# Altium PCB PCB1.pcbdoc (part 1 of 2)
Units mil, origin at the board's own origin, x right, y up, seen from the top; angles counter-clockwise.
Board outline 5175 x 2060 mil, 4 copper layers (Top Layer, Inner1, Inner2, Bottom Layer), stack 62.447 mil thick; 102 components, 59 nets, 316 pads, 177 vias.
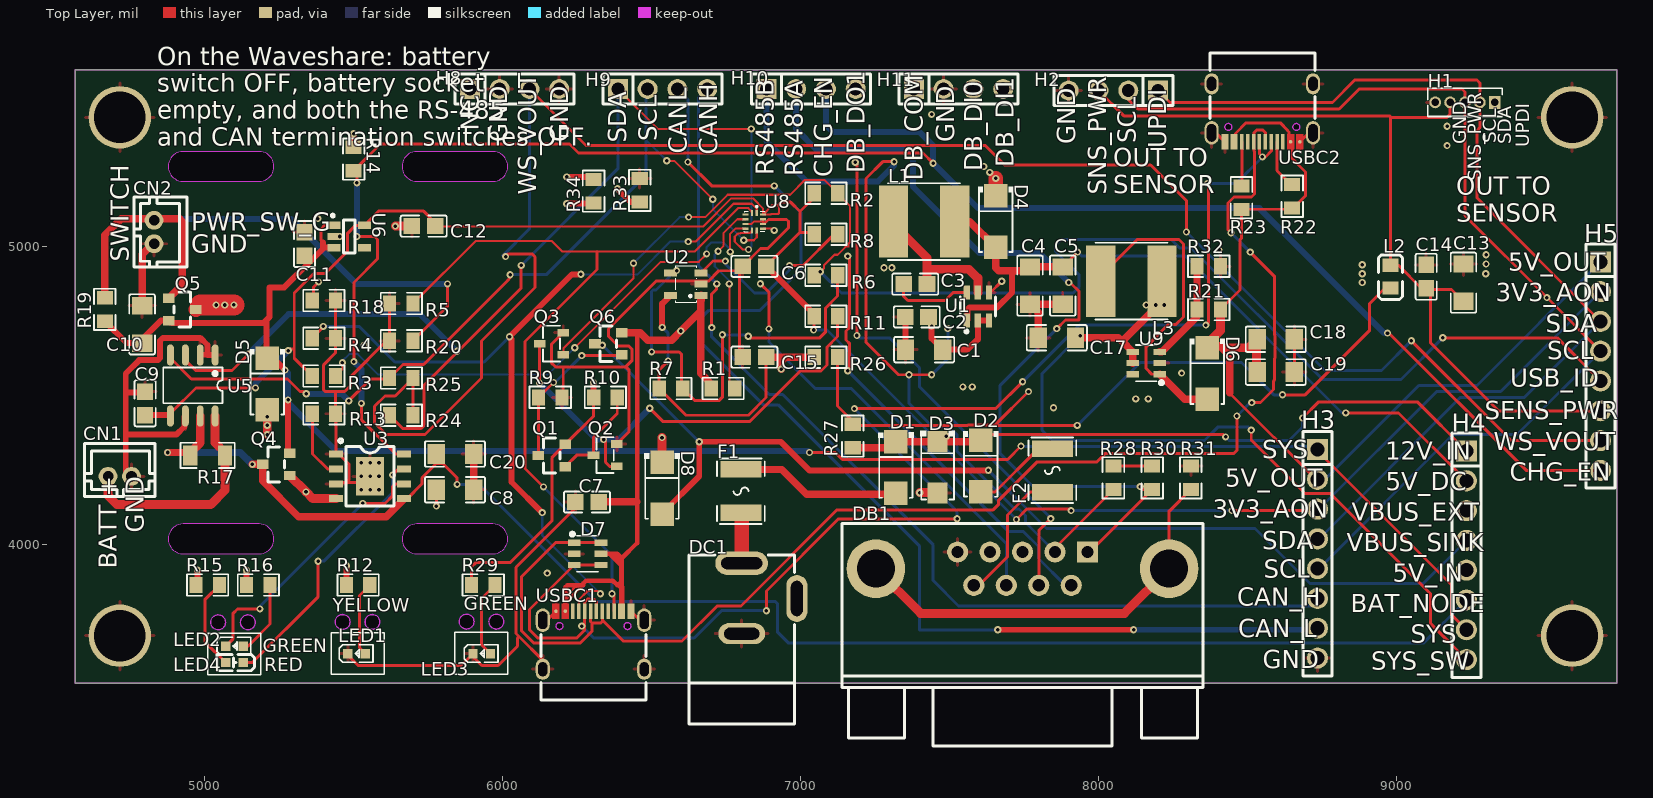
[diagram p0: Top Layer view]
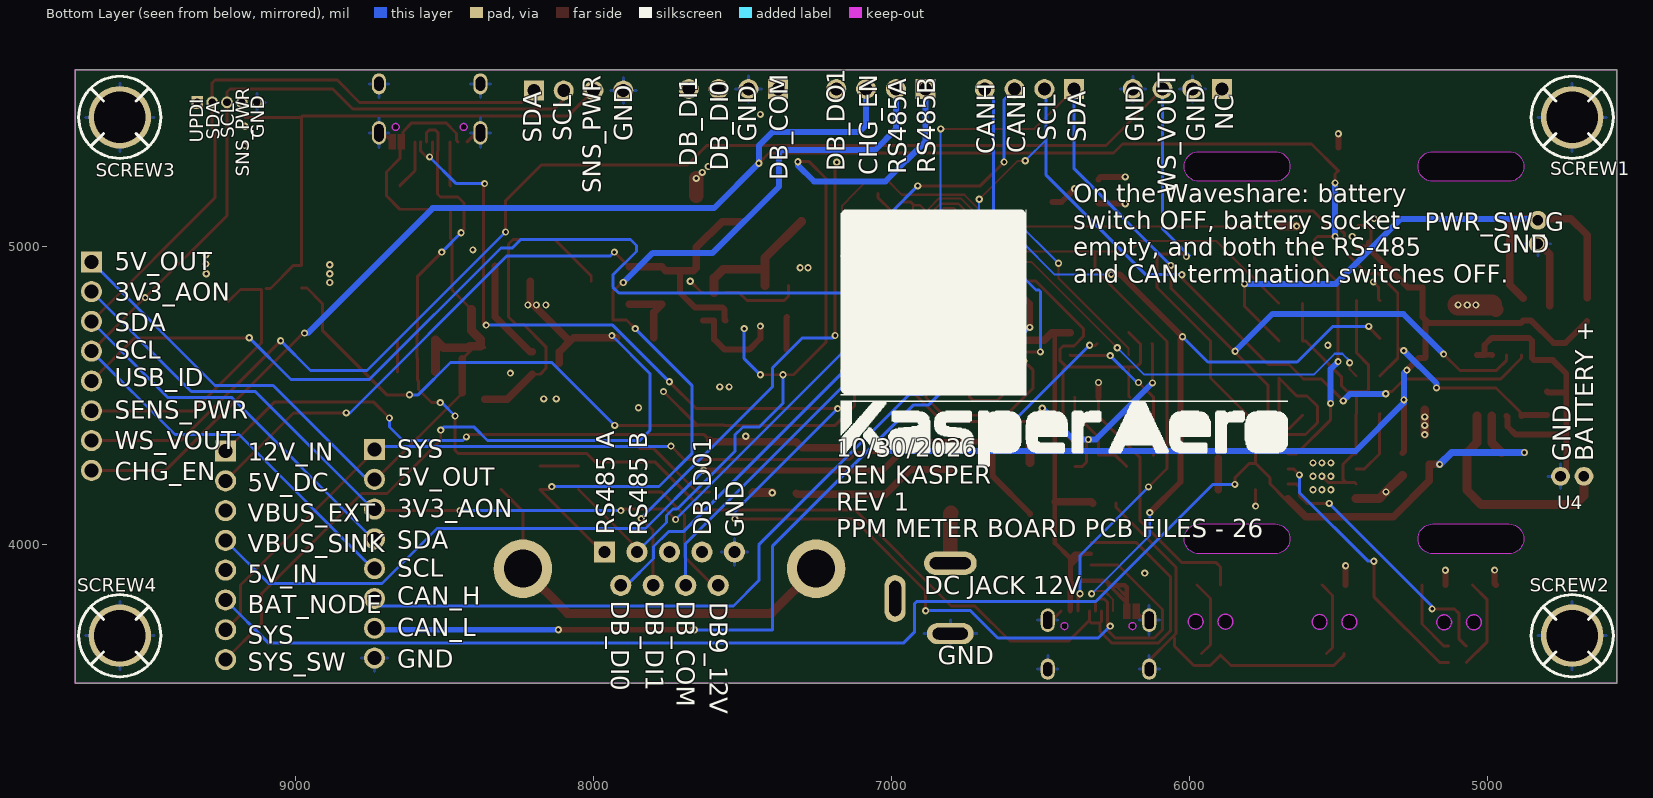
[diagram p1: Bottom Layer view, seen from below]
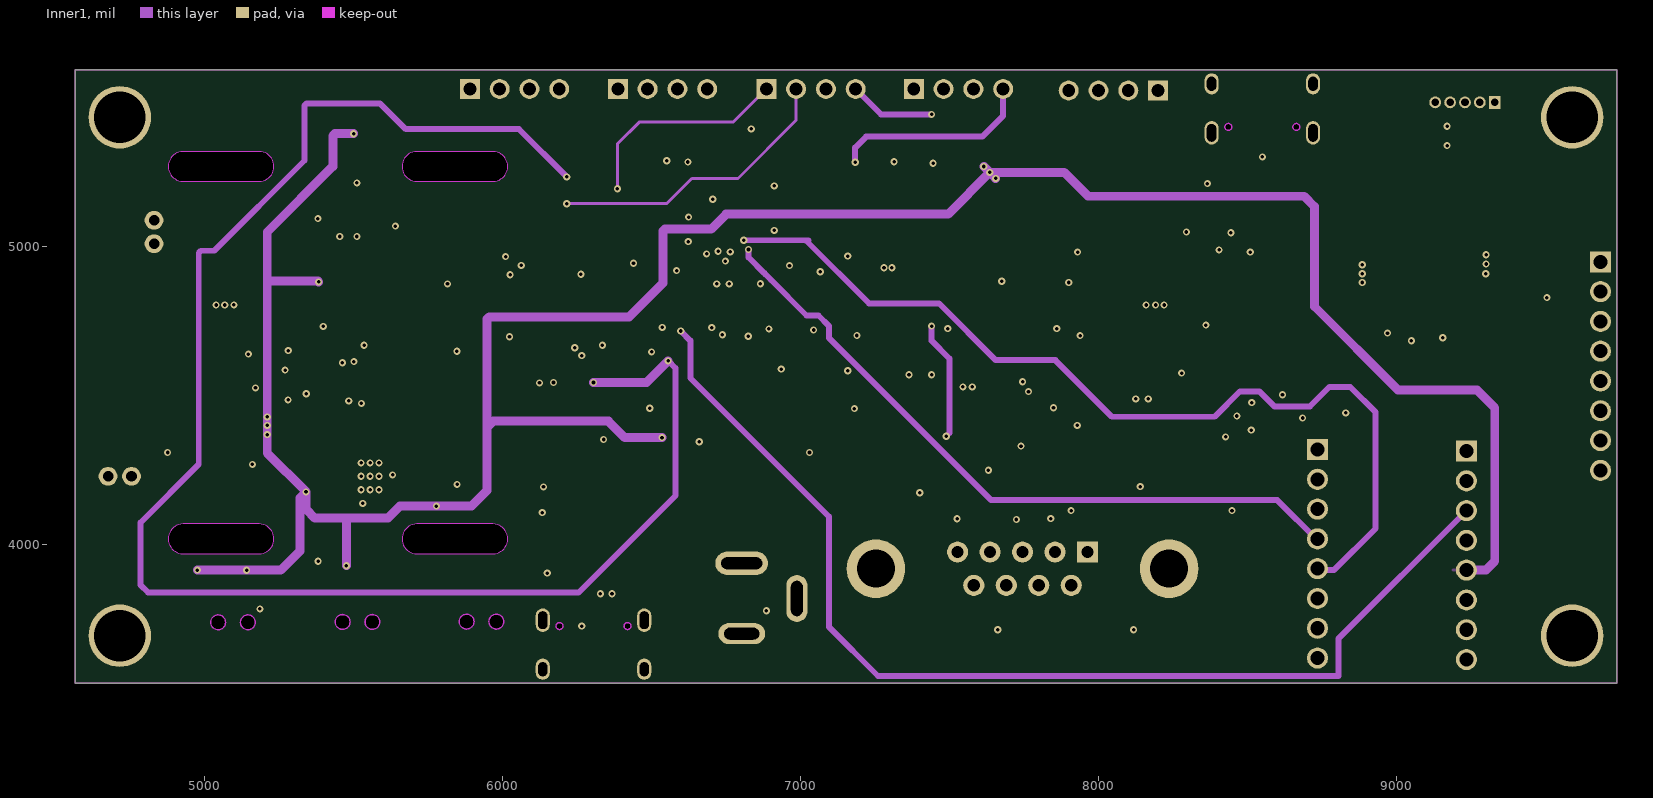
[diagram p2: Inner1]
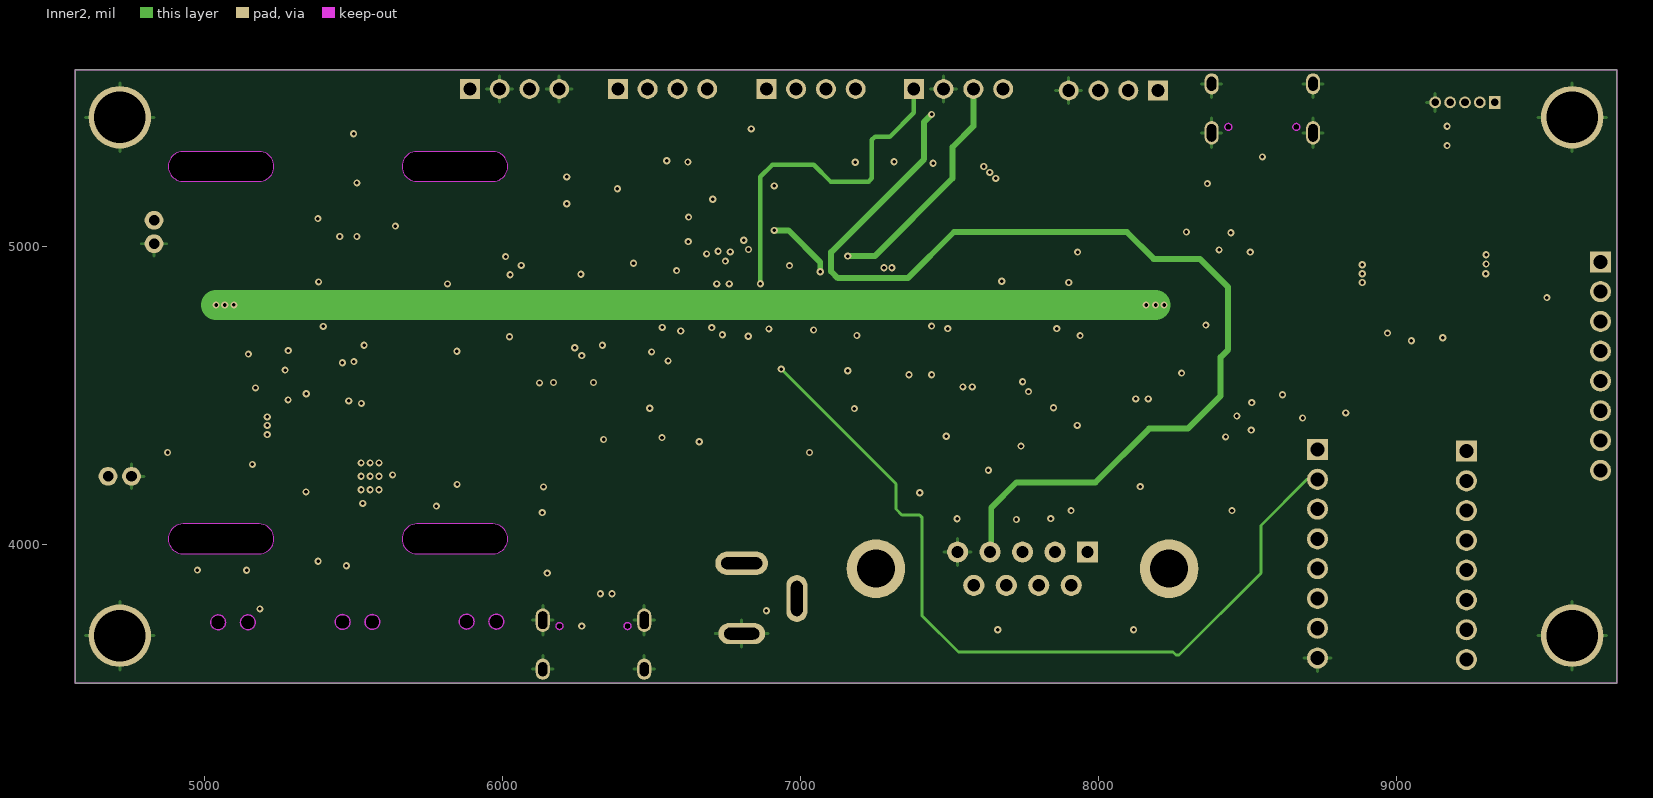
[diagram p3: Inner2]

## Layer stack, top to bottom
Top Layer: signal copper 1.378
Dielectric1: surface 8.283, 7628 RC49% 8.6mil, Dk 0
Inner1: signal copper 0.598
Dielectric2: surface 41.929, 1.1mm H/HOZ Copper, Dk 0
Inner2: signal copper 0.598
Dielectric3: surface 8.283, 7628 RC49% 8.6mil, Dk 0
Bottom Layer: signal copper 1.378

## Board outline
4565,5595 4565,3535 9740,3535 9740,5595
cut-out: 4927.5,5320 ccw(c4927.5,5270) 4877.5,5270 ccw(c4927.5,5270) 4927.5,5220 5182.5,5220 ccw(c5182.5,5270) 5232.5,5270 ccw(c5182.5,5270) 5182.5,5320
cut-out: 5712.5,5320 ccw(c5712.5,5270) 5662.5,5270 ccw(c5712.5,5270) 5712.5,5220 5967.5,5220 ccw(c5967.5,5270) 6017.5,5270 ccw(c5967.5,5270) 5967.5,5320
cut-out: 4927.5,4070 ccw(c4927.5,4020) 4877.5,4020 ccw(c4927.5,4020) 4927.5,3970 5182.5,3970 ccw(c5182.5,4020) 5232.5,4020 ccw(c5182.5,4020) 5182.5,4070
cut-out: 5712.5,4070 ccw(c5712.5,4020) 5662.5,4020 ccw(c5712.5,4020) 5712.5,3970 5967.5,3970 ccw(c5967.5,4020) 6017.5,4020 ccw(c5967.5,4020) 5967.5,4070
cut-out: 5070,3740 cw(c5045,3740) 5020,3740 cw(c5045,3740)
cut-out: 5170,3740 cw(c5145,3740) 5120,3740 cw(c5145,3740)
cut-out: 5488,3741.25 cw(c5463,3741.25) 5438,3741.25 cw(c5463,3741.25)
cut-out: 5588,3741.25 cw(c5563,3741.25) 5538,3741.25 cw(c5563,3741.25)
cut-out: 5904,3742.25 cw(c5879,3742.25) 5854,3742.25 cw(c5879,3742.25)
cut-out: 6004,3742.3 cw(c5979,3742.3) 5954,3742.3 cw(c5979,3742.3)

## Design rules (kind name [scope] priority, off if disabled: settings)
BoardOutlineClearance copperThickness1oz [All] p0: genericclearance=10 ignorepadtopadclearanceinfootprint=FALSE except(0: Arc-SplitContinuation Track-SplitContinuation SMDPad-SplitContinuation THPad-SplitContinuation Via-SplitContinuation Fill-SplitContinuation Poly-SplitContinuation Region-SplitContinuation Text-SplitContinuation)
BoardOutlineClearance copperThickness2oz [All] p0: genericclearance=10 ignorepadtopadclearanceinfootprint=FALSE except(0: Arc-SplitContinuation Track-SplitContinuation SMDPad-SplitContinuation THPad-SplitContinuation Via-SplitContinuation Fill-SplitContinuation Poly-SplitContinuation Region-SplitContinuation Text-SplitContinuation)
BoardOutlineClearance safeClearance1 [All] p0: genericclearance=10 ignorepadtopadclearanceinfootprint=FALSE except(0: Arc-SplitContinuation Track-SplitContinuation SMDPad-SplitContinuation THPad-SplitContinuation Via-SplitContinuation Fill-SplitContinuation Poly-SplitContinuation Region-SplitContinuation Text-SplitContinuation)
BoardOutlineClearance otherClearance [All] p0: genericclearance=10 ignorepadtopadclearanceinfootprint=FALSE except(0: Arc-SplitContinuation Track-SplitContinuation SMDPad-SplitContinuation THPad-SplitContinuation Via-SplitContinuation Fill-SplitContinuation Poly-SplitContinuation Region-SplitContinuation Text-SplitContinuation)
Clearance copperThickness1oz [All] p1: gap=7 ignorepadtopadclearanceinfootprint=FALSE
Clearance copperThickness2oz [All] p1: gap=7 ignorepadtopadclearanceinfootprint=FALSE
Clearance safeClearance1 [All] p1: gap=7 ignorepadtopadclearanceinfootprint=FALSE
Clearance otherClearance [All] p1: gap=7 ignorepadtopadclearanceinfootprint=FALSE
DiffPairsRouting differentialPair [All] p1: maxuncoupledlength=10 minlimit=6 maxlimit=Infinity mostfreqgap=6 toplayer_minwidth=5 toplayer_prefwidth=10 toplayer_maxwidth=100 bottomlayer_minwidth=5 bottomlayer_prefwidth=10 bottomlayer_maxwidth=100 midlayer1_minwidth=5 midlayer1_prefwidth=10 midlayer1_maxwidth=100 midlayer2_minwidth=5 midlayer2_prefwidth=10 midlayer2_maxwidth=100
PasteMaskExpansion pasteMaskExpansion [All] p1: expansion=0
PlaneConnect innerPlane [All] p1: planeconnectstyle=Relief reliefexpansion=20 reliefentries=4 reliefconductorwidth=10 reliefairgap=10
PolygonConnect copperRegion [All] p1: connectstyle=Relief reliefentries=4 reliefconductorwidth=10 polygonreliefangle="90 Angle" airgapwidth=10
RoutingVias viaSize [All] p1: viastyle="Through Hole" holewidth=12.0078 minholewidth=11.811 maxholewidth=248.0314 width=12.0078 minwidth=11.811 maxwidth=248.0314
SolderMaskExpansion solderMaskExpansion [IsVia] p1: useseparateexpansions=TRUE expansion=-1000 expansionbottom=-1000
SolderMaskExpansion solderMaskExpansion [All] p2: useseparateexpansions=TRUE expansion=2 expansionbottom=2
Width copperThickness1oz [All] p1: maxlimit=100 minlimit=5 preferedwidth=10
Width copperThickness2oz [All] p1: maxlimit=100 minlimit=8 preferedwidth=10

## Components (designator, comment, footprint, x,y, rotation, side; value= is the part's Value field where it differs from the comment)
C1 "22uF" C1206 7415,4655 r0 top
C2 "100nF" C0805 7390,4765 r0 top
C3 "100nF" C0805 7385,4875 r180 top
C4 "22uF" C1206 7770,4870 r90 top
C5 "22uF" C1206 7880,4870 r90 top
C6 "100nF" C0805 6845,4935 r0 top
C7 "1uF" C0805 6283.2,4143.7 r180 top
C8 "22uF" C1206 5840,4185 r180 top
C9 "100nF" C0805 4800,4475 r270 top
C10 "22uF" C1206 4790,4740 r270 top
C11 "1uF" C0805 5335,5010 r270 top
C12 "1uF" C0805 5735,5070 r0 top
C13 "22uF" C1206 9225,4880 r90 top
C14 "100nF" C0805 9100,4900 r270 top
C15 "100nF" C0805 6845,4630 r0 top
C17 "22uF" C1206 7860,4695 r180 top
C18 "22uF" C1206 8595,4690 r0 top
C19 "22uF" C1206 8595,4580 r0 top
C20 "22uF" C1206 5840,4305 r180 top
CN1 "B2B-PH-K-S(LF)(SN)" CONN-TH_B2B-PH-K-S 4715,4230 r0 top
CN2 "B2B-PH-K-S(LF)(SN)" CONN-TH_B2B-PH-K-S 4830,5050 r270 top
D1 "SS34" SMA_L4.3-W2.6-LS5.2-RD 7320,4260 r270 top
D2 "SS34" SMA_L4.3-W2.6-LS5.2-RD 7605,4264.23 r270 top
D3 "SMAJ18A" SMA_L4.4-W2.6-LS5.0-RD 7460,4260 r270 top
D4 "SS34" SMA_L4.3-W2.6-LS5.2-RD 7655,5085 r270 top
D5 "SS34" SMA_L4.3-W2.6-LS5.2-RD 5210,4540 r270 top
D6 "SS34" SMA_L4.3-W2.6-LS5.2-RD 8365,4575 r270 top
D7 "USBLC6-2SC6" SOT-23-6_L2.9-W1.6-P0.95-LS2.8-BL 6285,3970 r270 top
D8 "SS34" SMA_L4.3-W2.6-LS5.2-RD 6535,4190 r270 top
DB1 "A-DF 09 A/KG-T2S" DB9-TH_DB9F_C9900018961 7745,3920 r0 top
DC1 "PJ-002AH" DC-IN-TH_PJ-002AH 6895,3820 r270 top
F1 "BSMD1812-150-33V" F1812 6800,4180 r90 top
F2 "BSMD1812-150-33V" F1812 7845,4250 r90 top
H1 "GRPB051VWVN-RC" HDR-TH_5P-P1.27-V-M-1 9230,5485 r180 top
H2 "" HDR-TH_4P-P2.54-V-M 8050,5525 r180 top
H3 "" HDR-TH_8P-P2.54-V-F-1 8735,3970 r270 top
H4 "" HDR-TH_8P-P2.54-V-F-1 9235,3965 r270 top
H5 "" HDR-TH_8P-P2.54-V-F-1 9685,4600 r270 top
H8 "" HDR-TH_4P-P2.54-V-M 6040,5530 r0 top
H9 "" HDR-TH_4P-P2.54-V-M 6536.67,5530 r0 top
H10 "" HDR-TH_4P-P2.54-V-M 7035,5530 r0 top
H11 "" HDR-TH_4P-P2.54-V-M 7530,5530 r0 top
L1 "6.8uH" IND-SMD_L6.0-W6.0_SMNR6045 7415,5085 r180 top
L2 "BLM21PG221SN1D" L0805 8980,4900 r90 top
L3 "6.8uH" IND-SMD_L6.0-W6.0_SMNR6045 8110,4885 r0 top
LED1 "NCD0603Y2" LED0603-RD 5510,3635 r0 top
LED2 "KT-0603G" LED0603-RD 5100,3660 r0 top
LED3 "KT-0603G" LED0603-RD 5930,3635 r0 top
LED4 "KT-0603R" LED-SMD_L1.6-W0.8-R-RD 5100,3605 r180 top
Q1 "AO3401A" SOT-23_L2.9-W1.3-P1.90-LS2.4-BR 6165,4300 r0 top
Q2 "2N7002" SOT-23-3_L2.9-W1.3-P1.90-LS2.4-BR 6344.1,4300.97 r0 top
Q3 "2N7002" SOT-23-3_L2.9-W1.3-P1.90-LS2.4-BR 6164.1,4675 r0 top
Q4 "AO3401A" SOT-23_L2.9-W1.3-P1.90-LS2.4-BR 5240,4270 r0 top
Q5 "AO3401A" SOT-23_L2.9-W1.3-P1.90-LS2.4-BR 4925,4790 r180 top
Q6 "AO3401A" SOT-23_L2.9-W1.3-P1.90-LS2.4-BR 6355,4675 r0 top
R1 "910kΩ" R0805 6740,4525 r0 top
R2 "100kΩ" R0805 7085,5180 r0 top
R3 "100kΩ" R0805 5400,4566.67 r0 top
R4 "5.1kΩ" R0805 5400,4693.33 r0 top
R5 "5.1kΩ" R0805 5660,4810 r180 top
R6 "0Ω" R0805 7085,4905 r0 top
R7 "100kΩ" R0805 6565,4525 r0 top
R8 "10kΩ" R0805 7085,5042.5 r0 top
R9 "100kΩ" R0805 6160,4495 r0 top
R10 "100kΩ" R0805 6345,4495 r0 top
R11 "100kΩ" R0805 7085,4767.5 r0 top
R12 "1kΩ" R0805 5515,3865 r0 top
R13 "2kΩ" R0805 5400,4440 r0 top
R14 "10kΩ" R0805 5500,5295 r270 top
R15 "1kΩ" R0805 5010,3865 r0 top
R16 "1kΩ" R0805 5180,3865 r0 top
R17 "50mΩ" R1206 5010,4300 r180 top
R18 "100kΩ" R0805 5400,4820 r180 top
R19 "1kΩ" R0805 4665,4790 r90 top
R20 "0Ω" R0805 5660,4685 r180 top
R21 "75kΩ" R0805 8370,4790 r180 top
R22 "10kΩ" R0805 8650,5170 r90 top
R23 "10kΩ" R0805 8480,5165 r90 top
R24 "10kΩ" R0805 5660,4435 r0 top
R25 "10kΩ" R0805 5660,4560 r0 top
R26 "0Ω" R0805 7085,4630 r0 top
R27 "0Ω" R0805 7175,4365 r90 top
R28 "0Ω" R0805 8050,4225 r270 top
R29 "1kΩ" R0805 5935,3865 r0 top
R30 "120Ω" R0805 8180,4225 r90 top
R31 "0Ω" R0805 8310,4225 r90 top
R32 "10kΩ" R0805 8370,4935 r0 top
R33 "560Ω" R0805 6460,5190 r90 top
R34 "560Ω" R0805 6305.39,5187.1 r90 top
SCREW1 "" Screw-Hole-M4 4715,5434.98 r180 bottom
SCREW2 "" Screw-Hole-M4 4715,3695 r180 bottom
SCREW3 "" Screw-Hole-M4 9590,5435 r180 bottom
SCREW4 "" Screw-Hole-M4 9590,3695 r180 bottom
U1 "AP63205WU-7" TSOT-23-6_L2.9-W1.6-P0.95-LS2.8-BL 7595,4800 r0 top
U2 "TPS2041BDBVR" SOT-23-5_L3.0-W1.7-P0.95-LS2.8-BR 6615,4875 r0 top
U3 "TP4056-42-ESOP8" ESOP-8_L4.9-W3.9-P1.27-LS6.0-BL-EP 5555,4230 r270 top
U5 "INA219AIDR" SOIC-8_L4.9-W3.9-P1.27-LS6.0-BL 4960,4535 r180 top
U6 "AP2112K-3.3TRG1" SOT-25-5_L2.9-W1.6-P0.95-LS2.8-BL 5485,5035 r270 top
U8 "TUSB320IRWBR" X2QFN-12_L1.6-W1.6-P0.40-TL 6845,5085 r270 top
U9 "MT3608" SOT-23-6_L2.9-W1.6-P0.95-LS2.8-BL 8160,4610 r90 top
USBC1 "TYPE-C-31-M-12" USB-C_SMD-TYPE-C-31-M-12_1 6305,3680 r0 top
USBC2 "TYPE-C-31-M-12" USB-C_SMD-TYPE-C-31-M-12_1 8550,5450 r180 top

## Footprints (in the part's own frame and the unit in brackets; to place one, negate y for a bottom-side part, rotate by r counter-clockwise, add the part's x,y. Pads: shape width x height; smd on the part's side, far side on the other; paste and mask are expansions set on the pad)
C0805 [mm]
  rect 1.41x1.35 smd paste-100 mask+0.051: 1(-1,0) 2(1,0)
  silkscreen extent -1.96,-0.9 1.96,0.9
C1206 [mm]
  rect 1.485x1.728 smd paste-100 mask+0.051: 1(-1.593,0) 2(1.593,0)
  silkscreen extent -2.56,-1.09 2.56,1.09
CONN-TH_B2B-PH-K-S [mm]
  round 1.6 hole 0.9: 1(1,0) 2(-1,0)
  silkscreen extent -3,-1.7 3,2.8
DB9-TH_DB9F_C9900018961 [mm]
  rect 1.8x1.8 hole 1.05 paste+0 mask+0.05: 1(5.54,1.42)
  round 1.8 hole 1.05 paste+0 mask+0.05: 2(2.77,1.42) 3(0,1.42) 4(-2.77,1.42) 5(-5.54,1.42) 6(4.155,-1.42) 7(1.385,-1.42) 8(-1.385,-1.42) 9(-4.155,-1.42)
  round 5 hole 3.25 paste+0 mask+0.05: 10(-12.5,0) 11(12.5,0)
  silkscreen extent -15.4,-15.13 15.4,3.87
DC-IN-TH_PJ-002AH [mm]
  oval 2x4.5 hole 1 slot 3.5 at 90 deg copper offset 0.001,0: 1(-3.001,-2.35)
  oval 1.8x4 hole 1 slot 3 at 90 deg copper offset 0,0: 2(3,-2.35)
  oval 4x1.8 hole 1 slot 3 at 0 deg copper offset 0,0.001: 3(0,2.349)
  silkscreen extent -3.7,-6.85 10.7,2.15
ESOP-8_L4.9-W3.9-P1.27-LS6.0-BL-EP [mm]
  rect 0.6x1.2 smd: 1(-1.905,-2.908) 2(-0.635,-2.908) 3(0.635,-2.908) 4(1.905,-2.908) 5(1.905,2.908) 6(0.635,2.908) 7(-0.635,2.908) 8(-1.905,2.908)
  rect 3.3x2.4 smd: 9(0,0)
  silkscreen extent -3.2,-2.67 2.55,2.05
F1812 [mil]
  rect 55.38x137.76 smd paste-3937.01 mask+2: 1(-72.97,0) 2(72.97,0)
  silkscreen extent -110,-80 110,80
HDR-TH_4P-P2.54-V-M [mm]
  rect 1.7x1.7 hole 1.1: 1(-3.81,0)
  round 1.7 hole 1.1: 2(-1.27,0) 3(1.27,0) 4(3.81,0)
  silkscreen extent -5.08,-1.27 5.08,1.27
HDR-TH_5P-P1.27-V-M-1 [mm]
  rect 1x1.1 hole 0.65: 1(-2.54,0)
  round 1 hole 0.65: 2(-1.27,0) 3(0,0) 4(1.27,0) 5(2.54,0)
  silkscreen extent -3.17,-1.2 3.17,1.2
HDR-TH_8P-P2.54-V-F-1 [mm]
  rect 1.8x1.8 hole 1.2: 1(-8.89,0)
  round 1.8 hole 1.2: 2(-6.35,0) 3(-3.81,0) 4(-1.27,0) 5(1.27,0) 6(3.81,0) 7(6.35,0) 8(8.89,0)
  silkscreen extent -10.41,-1.25 10.41,1.25
IND-SMD_L6.0-W6.0_SMNR6045 [mm]
  rect 2.474x6.12 smd: 1(2.603,0) 2(-2.603,0)
  silkscreen extent -3.08,-3.28 3.08,3.28
L0805 [mil]
  rect 44.59x54.21 smd paste-3937.01 mask+2: 1(-38.04,0) 2(38.04,0)
  silkscreen extent -77,-40 73,40
LED0603-RD [mm]
  rect 0.8x0.8 smd: 1(-0.749,0) 2(0.749,0)
  silkscreen extent -1.49,-0.75 1.39,0.76
LED-SMD_L1.6-W0.8-R-RD [mm]
  rect 0.8x0.8 smd: 1(0.75,0) 2(-0.75,0)
  silkscreen extent -1.7,-0.7 1.47,0.7
R0805 [mm]
  rect 1.133x1.377 smd paste-100 mask+0.051: 1(-1,0) 2(1,0)
  silkscreen extent -1.76,-0.92 1.76,0.92
R1206 [mil]
  rect 47.54x66.97 smd paste-3937.01 mask+2: 1(-58.22,0) 2(58.22,0)
  silkscreen extent -91,-42 91,42
Screw-Hole-M4 [mil]
  round 210 hole 173.2: 1(0,0)
  silkscreen extent -138,-138 138,138
SMA_L4.3-W2.6-LS5.2-RD [mm]
  rect 2x2 smd: 1(-2.2,0) 2(2.2,0)
  silkscreen extent -2.98,-1.5 2.6,1.5
SMA_L4.4-W2.6-LS5.0-RD [mm]
  rect 1.8x1.7 smd paste+0 mask+0.051: 1(-2.192,0) 2(2.192,0)
  silkscreen extent -3.11,-1.48 2.73,1.48
SOIC-8_L4.9-W3.9-P1.27-LS6.0-BL [mm]
  oval 0.588x1.8 smd paste+0 mask+0.051: 1(-1.905,-2.6) 2(-0.635,-2.6) 3(0.635,-2.6) 4(1.905,-2.6) 5(1.905,2.6) 6(0.635,2.6) 7(-0.635,2.6) 8(-1.905,2.6)
  silkscreen extent -2.53,-1.52 2.53,1.52
SOT-23-3_L2.9-W1.3-P1.90-LS2.4-BR [mm]
  rect 1x0.65 smd: 1(1,-0.95) 2(1,0.95) 3(-1,0)
  silkscreen extent -0.73,-1.53 0.73,1.53
SOT-23-5_L3.0-W1.7-P0.95-LS2.8-BR [mm]
  rect 1.1x0.6 smd: 1(1.3,-0.95) 2(1.3,0) 3(1.3,0.95) 4(-1.3,0.95) 5(-1.3,-0.95)
  silkscreen extent -0.9,-1.55 0.9,1.55
SOT-23-6_L2.9-W1.6-P0.95-LS2.8-BL [mil]
  rect 20.95x42.2 smd: 1(-37.4,-45.24) 2(0,-45.24) 3(37.4,-45.24) 4(37.4,45.24) 5(0,45.24) 6(-37.4,45.24)
  silkscreen extent -72,-57 61,35
SOT-23_L2.9-W1.3-P1.90-LS2.4-BR [mm]
  rect 1x0.8 smd: 1(1.15,-0.95) 2(1.15,0.95) 3(-1.15,0)
  silkscreen extent -0.7,-1.5 0.7,1.5
SOT-25-5_L2.9-W1.6-P0.95-LS2.8-BL [mil]
  rect 24.5x43.5 smd: 1(-37.39,-51.18) 2(-0.02,-51.18) 3(37.39,-51.18) 4(37.39,51.18) 5(-37.39,51.18)
  silkscreen extent -75,-60 56,20
TSOT-23-6_L2.9-W1.6-P0.95-LS2.8-BL [mm]
  rect 0.55x1.2 smd: 1(-0.95,-1.2) 2(0,-1.2) 3(0.95,-1.2) 4(0.95,1.2) 5(0,1.2) 6(-0.95,1.2)
  silkscreen extent -1.5,-2.25 1.5,0.8
USB-C_SMD-TYPE-C-31-M-12_1 [mm]
  oval 1.2x2 hole 0.8 slot 1.5 at 90 deg paste+0 mask+0.051: 1(4.325,1.706) 4(-4.325,1.706)
  oval 1.2x1.8 hole 0.8 slot 1.2 at 90 deg copper offset 0,0 paste+0 mask+0.051: 2(4.325,-2.474) 3(-4.325,-2.474)
  round 0.3 smd: A1B12(-3.2,2.474) A4B9(-2.4,2.474)
  rect 0.3x1.3 smd paste-100 mask+0.051: A5(-1.25,2.474) A6(-0.25,2.474) A7(0.25,2.474) A8(1.25,2.474) B5(1.75,2.474) B6(0.75,2.474) B7(-0.75,2.474) B8(-1.75,2.474)
  rect 0.6x1.3 smd paste-100 mask+0.051: B1A12(3.2,2.474) B4A9(2.4,2.474)
  Top Layer region: -2.9,1.824 -2.9,3.124 -3.2,3.124 -3.2,3.124 -3.5,3.124 -3.5,1.824 -3.2,1.824 -3.2,1.824
  Top Layer region: -2.1,1.824 -2.1,3.124 -2.4,3.124 -2.4,3.124 -2.7,3.124 -2.7,1.824 -2.4,1.824 -2.4,1.824
  Board Outline Layer circle w0.003: c-2.9,1.206 r0.3
  Board Outline Layer circle w0.003: c2.9,1.206 r0.3
  Board Outline Layer region: -2.6,1.206 -2.63,1.075 -2.713,0.971 -2.833,0.913 -2.967,0.913 -3.087,0.971 -3.17,1.075 -3.2,1.206 -3.2,1.206 -3.17,1.336 -3.087,1.44 -2.967,1.498 -2.833,1.498 -2.713,1.44 -2.63,1.336 -2.6,1.206
  Board Outline Layer region: -2.6,1.206 -2.609,1.134 -2.634,1.066 -2.675,1.007 -2.729,0.959 -2.794,0.925 -2.864,0.908 -2.936,0.908 -3.006,0.925 -3.07,0.959 -3.124,1.007 -3.166,1.066 -3.191,1.134 -3.2,1.206 -3.191,1.277 -3.166,1.345 -3.124,1.405 -3.07,1.453 -3.006,1.486 -2.936,1.503 -2.864,1.503 -2.794,1.486 -2.729,1.453 -2.675,1.405 -2.634,1.345 -2.609,1.277
  Board Outline Layer region: 3.2,1.206 3.17,1.075 3.087,0.971 2.967,0.913 2.833,0.913 2.713,0.971 2.63,1.075 2.6,1.206 2.6,1.206 2.63,1.336 2.713,1.44 2.833,1.498 2.967,1.498 3.087,1.44 3.17,1.336 3.2,1.206
  Board Outline Layer region: 3.2,1.206 3.191,1.134 3.166,1.066 3.124,1.007 3.07,0.959 3.006,0.925 2.936,0.908 2.864,0.908 2.794,0.925 2.729,0.959 2.675,1.007 2.634,1.066 2.609,1.134 2.6,1.206 2.609,1.277 2.634,1.345 2.675,1.405 2.729,1.453 2.794,1.486 2.864,1.503 2.936,1.503 3.006,1.486 3.07,1.453 3.124,1.405 3.166,1.345 3.191,1.277
  Multi-Layer board cut-out: -2.6,1.206 -2.63,1.075 -2.713,0.971 -2.833,0.913 -2.967,0.913 -3.087,0.971 -3.17,1.075 -3.2,1.206 -3.2,1.206 -3.17,1.336 -3.087,1.44 -2.967,1.498 -2.833,1.498 -2.713,1.44 -2.63,1.336 -2.6,1.206
  Multi-Layer board cut-out: 3.2,1.206 3.17,1.075 3.087,0.971 2.967,0.913 2.833,0.913 2.713,0.971 2.63,1.075 2.6,1.206 2.6,1.206 2.63,1.336 2.713,1.44 2.833,1.498 2.967,1.498 3.087,1.44 3.17,1.336 3.2,1.206
  silkscreen extent -4.47,-5.09 4.47,0.49
X2QFN-12_L1.6-W1.6-P0.40-TL [mm]
  rect 0.505x0.2 smd: 1(-0.75,0.2) 2(-0.75,-0.2) 7(0.75,-0.2) 8(0.75,0.2)
  rect 0.2x0.505 smd: 3(-0.6,-0.75) 4(-0.2,-0.75) 5(0.2,-0.75) 6(0.6,-0.75) 9(0.6,0.75) 10(0.2,0.75) 11(-0.2,0.75) 12(-0.6,0.75)
  silkscreen extent -1.35,-0.87 0.86,0.87

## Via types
v1: diameter 24.02, hole 12, Top Layer to Bottom Layer, 177 vias

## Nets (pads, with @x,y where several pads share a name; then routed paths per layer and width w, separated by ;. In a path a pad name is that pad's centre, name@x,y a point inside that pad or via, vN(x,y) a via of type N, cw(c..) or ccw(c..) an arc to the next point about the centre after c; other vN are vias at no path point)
3V3_AON: C6.2 C9.2 C12.2 H3.3 H5.2 R2.1 R3.1 R8.1 R11.1 U5.5 U6.5 U8.12 | length 6842.2
  Top Layer w7.09: C12.2@5774.37,5070 5775.75,5068.62 6673.62,5068.62 6767.91,5162.91 6840.24,5162.91 6874.53,5128.62 U8.12@6874.53,5108.62 ; 6927.73,5113.88 6924.49,5110.64 6901.92,5110.64 6899.9,5108.62 U8.12@6874.53,5108.62 ; 6928.09,5114.24 6928.09,5136.28 6924.37,5140 6904.37,5140 U8.12@6874.53,5108.62
  Top Layer w10: U5.5@4885,4432.63 4890.63,4438.27 4890.63,4446.84 4970.63,4526.84 v1(5170.63,4526.84) ; v1(5280.63,4651.84) 5285.63,4656.84 5300.63,4656.84 ; R3.1@5360.63,4566.67 5300.63,4626.67 5300.63,4656.84 ; C12.2@5774.37,5070 5774.37,5080.63 5735,5120 5583.79,5120 U6.5@5536.18,5072.39 5506.18,5072.39 5480,5046.21 5480,4986.21 5403.79,4910 5365,4910 5300.63,4845.63 5300.63,4656.84 ; C6.2@6884.37,4935 6998.51,5049.14 ; 6924.37,5140 6934.37,5150 6967.02,5150 6998.51,5118.51 ; v1(7043.68,4721.01) 7045.63,4722.95 R11.1@7045.63,4767.5 ; R8.1@7045.63,5042.5 7038.99,5049.14 6998.51,5049.14 ; R2.1@7045.63,5180 7045.63,5165.63 6998.51,5118.51 ; v1(7724.44,4084.99) 7759.46,4120 7903.13,4120 v1(7908.13,4115) ; v1(8448.13,4115) H3.3@8735,4115 ; 6998.51,5049.14 6998.51,5118.51
  Top Layer w20: C9.2@4800,4435.63 4882.01,4435.63 U5.5@4885,4432.63 ; C6.2@6884.37,4935 7045.63,4773.74 R11.1@7045.63,4767.5
  Bottom Layer w10: v1(7043.68,4721.01) 7088.42,4721.01 v1(7724.44,4084.99) ; v1(7908.13,4115) v1(8448.13,4115) ; H3.3@8735,4115 9135,4515 9350,4515 H5.2@9685,4850
  Bottom Layer w20: v1(5170.63,4526.84) 5170.63,4541.84 v1(5280.63,4651.84)
5V_DC: C4.2 C5.2 D4.2 H4.2 L1.2 U1.1 | length 2468.8
  Top Layer w10: C5.2@7880,4932.7 v1(7930,4982.7) ; v1(8830,4442.7) 9007.29,4442.7 H4.2@9235,4215
  Top Layer w20: U1.1@7557.6,4752.76 7560,4755.16 7560,4790 7567.07,4797.07 7660,4797.07 7710,4847.07 7710,4909.53 7720.47,4920
  Top Layer w25: L1.2@7507.48,5085 7568.39,5085 D4.2@7655,4998.39 7655,4930 ; 7655,4929.53 7664.53,4920 7720.47,4920 7757.3,4920 C4.2@7770,4932.7 C5.2@7880,4932.7
  Bottom Layer w10: v1(7930,4982.7) 7942.7,4970 8290,4970 8817.3,4442.7 v1(8830,4442.7)
5V_IN: C8.2 D4.1 D5.2 D8.1 H4.5 Q4.1 R12.1 R14.1 R15.1 R16.1 R18.2 U3.4 | length 9878.7
  Top Layer w10: R18.2@5360.63,4820 5365,4824.37 5365,4865 v1(5382.5,4882.5) ; C8.2@5777.3,4185 5777.66,4184.64 v1(5777.66,4130)
  Top Layer w20: R15.1@4970.63,3865 4975.63,3870 v1(4975.63,3915.04) ; R16.1@5140.63,3865 v1(5140.63,3915) ; R12.1@5475.63,3865 v1(5475.63,3930) ; R14.1@5500,5334.37 v1(5500,5380)
  Top Layer w30: v1(5210,4370) v1(5210,4400.76) v1(5210,4429.31) D5.2@5210,4453.39 ; Q4.1@5285.27,4232.6 v1(5340.14,4177.74) 5362.88,4155 U3.4@5440.5,4155 ; D8.1@6535,4276.61 v1(6535,4360)
  Top Layer w50: D4.1@7655,5171.61 v1(7655,5230)
  Inner1 w30: v1@4975.67,3915 v1(5140.63,3915) 5255,3915 5320,3980 5320,4157.6 v1(5340.14,4177.74) ; v1(5382.5,4882.5) 5379.84,4885.16 5210,4885.16 ; v1(5475.63,3930) 5475.63,4085.99 5479.64,4090 ; v1(5500,5380) 5437.07,5380 5430,5372.93 5430,5270 5210,5050 5210,4885.16 ; v1(6535,4360) 6410,4360 6355,4415 5969,4415 5947.93,4393.93 ; v1(7615,5270) v1(7635,5250) ; v1(7655,5230) v1(7635,5250) ; H4.5@9235,3915 9300,3915 9330,3945 9330,4460 9270,4520 9005,4520 8725,4800 8725,5135 8690,5170 7965,5170 7885,5250 v1(7635,5250) ; 5210,4885.16 v1(5210,4429.31) v1(5210,4400.76) v1(5210,4370) 5210,4307.88 v1(5340.14,4177.74) ; v1(5340.14,4177.74) 5340.14,4119.86 5370,4090 5479.64,4090 ; 5479.64,4090 5615,4090 5655,4130 v1(5777.66,4130) 5895,4130 5947.93,4182.93 5947.93,4393.93 ; 5947.93,4393.93 5947.93,4757.93 5955,4765 6425,4765 6537.93,4877.93 6537.93,5052.93 6545,5060 6700,5060 6750,5110 7495,5110 v1(7635,5250)
5V_OUT: C15.2 C18.1 C19.1 D6.1 H3.2 H5.1 Q1.2 R7.1 R10.1 R21.1 R22.1 R23.1 R26.1 R29.1 R34.2 U2.5 USBC2.A4B9 USBC2.B4A9 | length 13837.6
  Top Layer w10: R29.1@5895.63,3865 5895.63,3925.63 5910,3940 6025,3940 6165,4080 6165,4292.12 Q1.2@6210.27,4337.4 6305.63,4432.76 R10.1@6305.63,4495 ; v1(6555.63,4617.48) 6525.63,4587.48 R7.1@6525.63,4525 6615.63,4435 6825,4435 6884.37,4494.37 C15.2@6884.37,4630 ; R21.1@8409.37,4790 8475,4855.63 8475,5023.82 8480,5028.82 8480,5126.41 8650,5126.41 8695,5171.41 8695,5251.41 8650,5296.41 8650,5346.41 ; 8440,4510 H3.2@8735,4215 ; 8440,4625 D6.1@8403.39,4661.61 ; USBC2.B4A9@8455.5,5352.59 8460,5357.09 8460,5381 8495.41,5416.41 8610,5416.41 8634.56,5391.85 8634.56,5390.27 8639,5385.83 8639,5357.41 8650,5346.41 ; C19.1@8530.58,4581.72 C19.1@8532.3,4580 ; USBC2.A4B9@8644.49,5352.6 8650,5347.09 8650,5346.41 ; D6.1@8403.39,4661.61 D6.1@8365,4661.61 D6.1@8403.39,4661.61
  Top Layer w20: v1(6215,5235) 6296.85,5235 R34.2@6305.39,5226.47 ; v1(6305,4545) 6305,4495.63 R10.1@6305.63,4495 ; v1(6535.63,4730) 6535.63,4809.41 U2.5@6563.81,4837.6
  Top Layer w25: C15.2@6884.37,4630 6949.2,4630 ; v1(6935,4590) 6935,4615.8 6949.2,4630 ; R26.1@7045.63,4630 6949.2,4630 ; 8440,4510 8440,4625
  Top Layer w30: R21.1@8409.37,4790 8409.37,4719.37 8380,4690 8380,4666.61 8415,4666.61 8420,4661.61 8503.91,4661.61 8530.58,4688.28 C19.1@8530.58,4581.72
  Inner1 w20: v1(6215,5235) 6055,5395 5675,5395 5587.93,5482.07 5342.07,5482.07 5335,5475 5335,5290 5032.07,4987.07 4987.07,4987.07 4980,4980 4980,4270 4785,4075 4785,3865 4810,3840 6255,3840 6580,4165 6580,4593.11 v1(6555.63,4617.48)
  Inner1 w30: v1(6305,4545) 6483.15,4545 v1(6555.63,4617.48)
  Inner2 w10: v1(6935,4590) 7320,4205 7320,4120 7340,4100 7400,4100 7407.07,4092.93 7407.07,3762.93 7530,3640 8250,3640 8260,3630 8270,3630 8545,3905 8545,4065 8700,4220 H3.2@8735,4220
  Bottom Layer w10: v1(6535.63,4730) 6555.63,4710 v1(6555.63,4617.48) ; H3.2@8735,4215 8755,4215 9075,4535 9270,4535 H5.1@9685,4950
12V_IN: C1.2 C2.2 D1.1 D2.1 D3.1 H4.1 R27.1 U1.2 U1.3 | length 2952.4
  Top Layer w10: D2.1@7610,4350.84 7630,4370.84 8418.25,4370.84 v1(8426.59,4362.49) ; v1(8685,4425.84) 8739.16,4480 9070,4480 H4.1@9235,4315
  Top Layer w20: v1(7440,4733.99) 7440,4692.7 C1.2@7477.7,4655 7560,4655 7595,4690 U1.2@7595,4752.76 U1.3@7632.4,4752.76
  Top Layer w25: R27.1@7175,4325.63 7299.02,4325.63 D1.1@7320,4346.61 7320.29,4346.32 D3.1@7460,4346.32 7605.48,4346.32 D2.1@7610,4350.84
  Inner1 w20: v1(7440,4733.99) 7440,4685 7500,4625 7500,4375.31 v1(7489.08,4364.39)
  Bottom Layer w10: v1(8426.59,4362.49) 8438.47,4350.61 8639.78,4350.61 8685,4395.84 v1(8685,4425.84)
$1N323: C3.2 U1.6 | length 264.8
  Top Layer w10: C3.2@7345.63,4870 7345.63,4834.37 7360,4820 7485,4820 7512.24,4847.24 U1.6@7557.6,4847.24
BAT_NODE: C20.2 H4.6 Q4.3 R17.2 U3.5 U5.7 | length 5188.8
  Top Layer w10: U3.5@5669.5,4155 5679.5,4155 5729.5,4205 5729.5,4225 C20.2@5777.3,4272.8 ; C20.2@5777.3,4305 C20.2@5777.3,4272.8 ; v1(5847.3,4202.8) 5847.3,4224.68 5799.18,4272.8 C20.2@5777.3,4272.8
  Top Layer w25: v1(4875.65,4310) R17.2@4951.78,4310 ; v1(5160,4270) Q4.3@5194.73,4270 5194.73,4215.27 5315,4095 5609.5,4095 U3.5@5669.5,4155
  Top Layer w30: R17.2@4951.78,4310 4985,4343.22 U5.7@4985,4432.63
  Bottom Layer w10: v1(5847.3,4202.8) 5921.7,4202.8 6314.5,3810 6915,3810 6922.07,3802.93 6922.07,3707.93 6960,3670 9090,3670 H4.6@9235,3815
  Bottom Layer w25: v1(4875.65,4310) 5120,4310 v1(5160,4270)
BATT_P: CN1.2 R17.1 U5.8 | length 743.2
  Top Layer w30: CN1.2@4675.63,4220 4675.63,4165 4705.63,4135 5020,4135 5068.22,4183.22 5068.22,4310 5035,4343.22 U5.8@5035,4432.63
BOOST_FB: R21.2 R32.1 U9.3 | length 343.7
  Top Layer w25: U9.3@8205.24,4647.4 8212.4,4647.4 8330.63,4765.63 R21.2@8330.63,4790 R32.1@8330.63,4935
BOOST_SW: D6.2 L3.2 U9.1 | length 1084.4
  Top Layer w10: L3.2@8007.52,4885 8007.52,4902.52 8130,5025 8270,5025 8285,5010 8285,4765 8260,4740 8235,4740 8160,4665 8160,4591.74 8179.14,4572.6 U9.1@8205.24,4572.6
  Top Layer w25: U9.1@8205.24,4572.6 8289.45,4488.39 D6.2@8365,4488.39
BUCK_SW: C3.1 L1.1 U1.5 | length 498.7
  Top Layer w30: L1.1@7302.52,5085 7424.37,4963.15 7424.37,4930.79 ; C3.1@7424.37,4870 7424.37,4930.79 ; U1.5@7595,4847.24 7595,4895 7565,4925 7430.16,4925 7424.37,4930.79
CANH: H3.6 H9.4 | length 3362.7
  Top Layer w10: v1(6701.67,4728.99) 6701.67,4841.67 6718.44,4858.44 v1(6718.44,4876.01)
  Bottom Layer w10: H9.4@6686.67,5530 6656.67,5500 6656.67,4937.78 v1(6718.44,4876.01) ; v1(6701.67,4728.99) 6701.67,4698.33 6895,4505 6940,4505 7445,4000 7445,3880 7530,3795 8715,3795 H3.6@8735,3815
CANL: H3.7 H9.3 | length 4022.8
  Top Layer w10: v1(6621.67,5285) 6701.67,5205 v1(6911.67,5205)
  Top Layer w20: v1(7661.67,3715) v1(8118,3715)
  Bottom Layer w10: H9.3@6586.67,5530 6621.67,5495 v1(6621.67,5285) ; v1(6911.67,5205) 7001.67,5115 7001.67,4925 6863.74,4787.07 6692.07,4787.07 6660,4755 6660,4685 6875,4470 6925,4470 7400,3995 7400,3715 v1(7661.67,3715)
  Bottom Layer w20: v1(8118,3715) H3.7@8735,3715
CC1: R4.1 U8.1 USBC1.A5 | length 2915.9
  Top Layer w7.09: USBC1.A5@6255.79,3777.41 6255.79,3815.79 6285,3845 6319.15,3845 v1(6328.14,3836.01) ; v1(6622.87,5018.02) 6648.02,5018.02 6775,5145 6835.89,5145 6852.87,5128.02 U8.1@6852.87,5114.53
  Top Layer w10: R4.1@5360.63,4693.33 5398.19,4730.89 v1(5398.19,4733.33)
  Top Layer w20: v1(6132.87,4108.02) 6030,4210.89 6030,4691.52 v1(6023.19,4698.33) 6232.87,4908.02 v1(6262.87,4908.02)
  Bottom Layer w7.09: v1(6132.87,4108.02) 6132.87,4031.28 v1(6328.14,3836.01) ; v1(6262.87,4908.02) 6453.02,4908.02 6563.02,5018.02 v1(6622.87,5018.02)
  Bottom Layer w10: v1(5398.19,4733.33) 5518.19,4733.33 5638.19,4613.33 5938.19,4613.33 v1(6023.19,4698.33)
CC2: R5.1 U8.2 USBC1.B5 | length 2739.3
  Top Layer w7.09: R5.1@5699.37,4810 5909.37,5020 6165,5020 6200.47,4984.53 6317.13,4984.53 6644.53,4984.53 6790,5130 6825,5130 6835.96,5119.04 6835.96,5115.71 U8.2@6837.13,5114.53
  Top Layer w10: v1(6137.13,4194.53) 6075,4256.66 6075,4682.4 6317.13,4924.53 6317.13,4984.53 ; v1(6367.13,3836.01) 6373.9,3829.24 USBC1.B5@6373.9,3777.41
  Bottom Layer w10: v1(6137.13,4194.53) 6367.13,3964.53 v1(6367.13,3836.01)
CHG_EN: H5.8 H10.3 R14.2 U3.8 | length 6382.3
  Top Layer w10: v1(5500.88,4615) 5500.88,4880.88 5580,4960 5580,5025 5570,5035 v1(5510.88,5035) ; v1(5510.88,5215) 5510.88,5244.75 R14.2@5500,5255.63 5590,5345.63 6224.37,5345.63 6255,5315 7410.62,5315 v1(7444.99,5280.63) ; v1(5525.88,4475) 5525.88,4420 5640.88,4305 U3.8@5669.5,4305 ; v1(8969.99,4710.63) 8974.99,4710.63 9435.62,4250 H5.8@9685,4250
  Bottom Layer w20: v1(5500.88,4615) 5525.88,4590 v1(5525.88,4475) ; v1(5510.88,5035) v1(5510.88,5215) ; H10.3@7085,5530 7085,5410 7110,5385 7400,5385 7444.99,5340.01 v1(7444.99,5280.63) 7595.62,5130 8540,5130 8959.37,4710.63 v1(8969.99,4710.63)
CHRG_N: LED4.2 U3.7 | length 913.6
  Top Layer w10: LED4.2@5129.53,3605 5160,3605 5380.88,3825.88 v1(5380.88,3945) ; v1(5630.88,4235) 5650.88,4255 U3.7@5669.5,4255
  Bottom Layer w10: v1(5380.88,3945) 5400,3945 5630.88,4175.88 v1(5630.88,4235)
DB9_12V: DB1.9 F2.1 | length 475.7
  Top Layer w10: DB1.9@7581.42,3864.09 7584.36,3867.03 7601.12,3867.03 7695,3960.91 7695,4079.07 7694.44,4079.63 7694.44,4100.35 7771.12,4177.03 F2.1@7845,4177.03
DB9_12V_F: D2.2 F2.2 | length 295.2
  Top Layer w10: D2.2@7610,4177.62 7652.62,4177.62 7797.97,4322.97 F2.2@7845,4322.97
DB_COM: DB1.8 H11.1 | length 2589.8
  Top Layer w10: v1(6865.11,4876.45) 6893.75,4847.81 v1(6893.75,4724.99)
  Inner2 w15: v1(6865.11,4876.45) 6865.11,5235.11 6905.75,5275.75 7044.25,5275.75 7100.61,5219.39 7228.79,5219.39 7239.39,5230 7239.39,5359.39 7250,5370 7300,5370 7380,5450 H11.1@7380,5530
  Bottom Layer w10: v1(6893.75,4724.99) 6893.75,4680.83 7050.49,4524.09 7170.91,4524.09 7690.49,4004.51 DB1.8@7690.48,3864.09
DB_DI0: DB1.6 H11.3 | length 2260.8
  Top Layer w10: v1(7158.6,4584.09) 7165,4590.5 7165,4675 7152.5,4687.5 7152.5,4717.5 7165,4730 7165,4962.69 v1(7158.6,4969.09)
  Inner2 w20: v1(7158.6,4969.09) 7249.09,4969.09 7510,5230 7510,5335 7580,5405 H11.3@7580,5530
  Bottom Layer w10: v1(7158.6,4584.09) 7698.6,4044.09 7748.6,4044.09 7798.6,3994.09 7798.6,3954.09 7888.6,3864.09 DB1.6@7908.59,3864.09
DB_DI1: DB1.7 H11.4 | length 2448.2
  Top Layer w10: v1(7183.33,5284.09) 7189.05,5278.37 v1(7189.05,4702.65) ; DB1.7@7799.53,3864.09 7799.54,4048.08 v1(7839.54,4088.08)
  Inner1 w20: v1(7183.33,5284.09) 7183.33,5333.33 7220,5370 7610,5370 7680,5440 H11.4@7680,5530
  Bottom Layer w10: v1(7189.05,4702.65) 7196.7,4695 7298.63,4695 7399.54,4594.09 7399.54,4530.46 7839.54,4090.46 v1(7839.54,4088.08)
DB_DO1: DB1.4 H10.4 | length 3891.4
  Inner1 w20: H10.4@7185,5530 7270,5445 v1(7440,5445)
  Inner2 w20: v1(7440,5445) 7415,5420 7415,5294.49 7102.76,4982.24 7102.76,4917.24 7125,4895 7360,4895 7515,5050 8095,5050 8185,4960 8340,4960 8435,4865 8435,4655 8410,4630 8410,4500 8300,4390 8170,4390 7990,4210 7725,4210 7640,4125 7640,3979.96 DB1.4@7635.94,3975.9
DB_SHELL: DB1.10 DB1.11 R31.1 | length 1404.3
  Top Layer w10: DB1.11@8237.13,3920 8237.13,4112.75 R31.1@8310,4185.63
  Top Layer w30: DB1.10@7252.88,3920 7402.88,3770 8087.12,3770 DB1.11@8237.13,3920
DC_JACK: DC1.1 F1.1 | length 169.9
  Top Layer w50: F1.1@6800,4107.03 6802.48,4104.55 6802.48,3978.11 DC1.1@6802.48,3938.14
DC_JACK_F: D1.2 F1.2 | length 555.8
  Top Layer w25: F1.2@6800,4252.97 6937.03,4252.97 7020,4170 7316.61,4170 D1.2@7320,4173.39
GND: C1.1 C2.1 C4.1 C5.1 C6.1 C7.2 C8.1 C9.1 C10.1 C11.1 C12.1 C13.2 C14.1 C15.1 C17.2 C18.2 C19.2 C20.1 CN1.1 CN2.1 D3.2 D7.2 DB1.5 DC1.2 H1.5 H2.4 H3.8 H8.2 H8.4 H11.2 LED1.1 LED3.1 Q2.2 Q3.2 R4.2 R5.2 R9.2 R13.2 R18.1 R20.2 R31.2 R32.2 R33.2 SCREW1.1 SCREW2.1 SCREW3.1 SCREW4.1 U1.4 U2.2 U3.1 U3.3 U3.9 U5.1 U5.2 U5.6 U6.2 U8.5 U8.10 U8.11 U9.2 USBC1.1 USBC1.2 USBC1.3 USBC1.4 USBC1.A1B12 USBC1.B1A12 USBC2.1 USBC2.2 USBC2.3 USBC2.4 USBC2.A1B12 USBC2.B1A12 | length 7052.8
  Top Layer w7.09: U8.5@6815.47,5077.13 6835.47,5077.13 6843.33,5085 6873.33,5085 ; U8.10@6874.53,5077.13 6873.33,5078.33 6873.33,5085 ; U8.11@6874.53,5092.87 6873.33,5091.68 6873.33,5085
  Top Layer w10: R18.1@5439.37,4820 R4.2@5439.37,4693.33 5439.37,4644.37 5399.37,4604.37 5399.37,4519.37 5403.74,4515 5439.37,4515 5439.37,4510.63 ; U3.3@5440.5,4205 5445.5,4210 5475,4210 ; LED1.1@5480.43,3635 5480.43,3629.57 5515,3595 5860.52,3595 5895.26,3629.74 5930,3595 5985,3595 6050,3660 6050,3687.87 6054.72,3692.59 ; v1(5555,4230) 5535,4210 5475,4210 ; R5.2@5620.63,4810 R20.2@5620.63,4685 5610.63,4685 5490,4564.37 5490,4535 5470,4515 5440.63,4515 5440,4514.37 5440,4511.26 5439.37,4510.63 ; USBC1.3@6134.73,3582.59 6134.72,3612.59 6054.72,3692.59 ; USBC1.4@6134.73,3747.15 6148.77,3747.15 USBC1.A1B12@6179.02,3777.41 ; R9.2@6199.37,4495 6203.47,4499.09 6203.47,4597.72 ; Q3.2@6203.47,4712.4 6163.47,4672.4 6163.47,4611.53 6177.28,4597.72 6203.47,4597.72 ; C7.2@6245.63,4140 6245.63,4125.63 6044.72,3924.72 6044.72,3702.59 6054.72,3692.59 ; Q2.2@6383.47,4338.37 6423.46,4378.37 6423.46,4587.72 6413.46,4597.72 ; USBC1.B1A12@6430.98,3777.41 6461.24,3747.15 USBC1.1@6475.27,3747.15 ; C15.1@6805.63,4630 6795.63,4640 6795.63,4920 6725.63,4920 6690.63,4885 6515,4885 6355,4725 6355,4700 6387.28,4667.72 6423.46,4667.72 6433.46,4657.72 6433.46,4617.72 6413.46,4597.72 ; C6.1@6805.63,4935 6865.63,4995 6890,4995 6960,5065 6960,5085 6952.93,5092.07 6892.07,5092.07 U8.10@6880,5080 ; U1.4@7632.4,4847.24 7637.71,4847.24 v1(7675.47,4885) ; USBC2.1@8379.73,5382.85 8393.76,5382.85 USBC2.B1A12@8424.01,5352.59 ; C19.2@8657.7,4580 C18.2@8657.7,4690 ; USBC2.A1B12@8675.98,5352.6 8706.23,5382.85 USBC2.4@8720.27,5382.85 ; 5439.37,4510.63 R13.2@5439.37,4440 5440.5,4438.86 U3.1@5440.5,4305 5450,4305 5485,4270 5485,4220 5475,4210 ; 6203.47,4597.72 6413.46,4597.72
  Top Layer w20: CN1.1@4754.37,4220 4750,4220 4735,4235 4735,4370 ; C9.1@4800,4514.37 4797.01,4511.38 4735,4511.38 ; U5.6@4935,4432.63 4932.35,4430 4932.35,4397.35 4905,4370 4735,4370 ; U5.2@4985,4637.37 4985.63,4637.99 5009.37,4637.99 ; U5.1@5035,4637.37 5010,4637.36 5009.37,4637.99 ; C2.1@7350.63,4765 7352.3,4763.33 C1.1@7352.3,4655 ; 4735,4370 4735,4511.38 ; 4735,4511.38 4735,4575 4780,4620 4842.57,4620 4850,4627.43 4850,4685 4860,4695 4985,4695 5009.37,4670.63 5009.37,4637.99
  Top Layer w25: C10.1@4790,4802.7 4790,4975.63 CN2.1@4830,5015.63 ; C8.1@5902.7,4185 C20.1@5902.7,4290 ; C17.2@7797.3,4695 7797.3,4780 C4.1@7770,4807.3 C5.1@7880,4807.3
  Top Layer w30: v1(5640.02,5070) C12.1@5695.63,5070 ; v1(7400,4175) 7463.68,4175 D3.2@7465,4173.68
  other v1: 6150,3905 5525,4185 5555,4185 5585,4185 5525,4230 5585,4230 5525,4275 5555,4275 5585,4275 7849.01,4460 8125,4490 8166.88,4490 7545,4530 7576.11,4530 8278.74,4576.26 5535,4670 8885,4880.56 8885,4910 9300,4910 7280,4930 7306.69,4930 8885,4940 9301.16,4942.7 9301.16,4973.54 8405,4990 5453.5,5035.02 5380,5095 9170,5340 9170,5405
